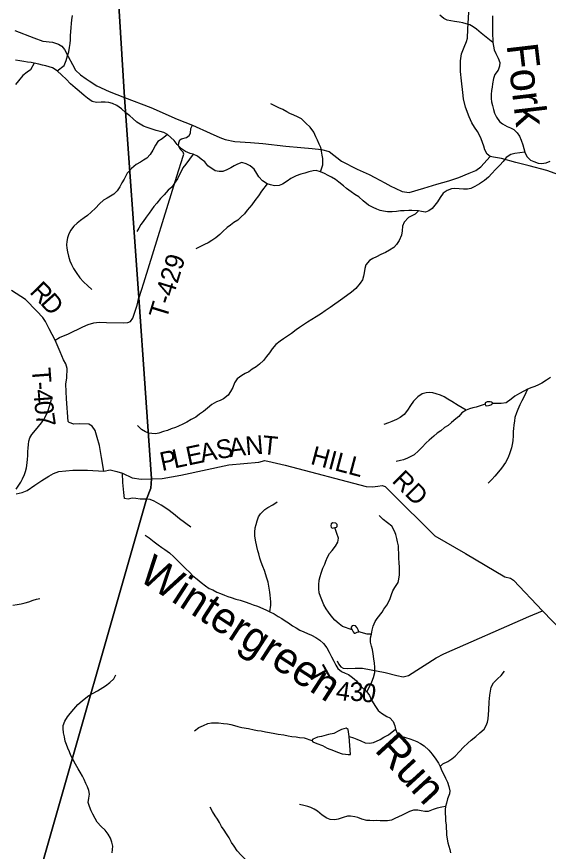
# Model space of a CAD drawing. Extents: x 1578669 to 1989827, y 208020 to 553079.
# Drawn here: x 1811019 to 1819546, y 411669 to 425058 of the extents above; entities that cross this region are included whole.
import ezdxf

# ---------------------------------------------------------------- set-up
doc = ezdxf.new("R2010")
doc.units = 0
for name, color, linetype in [('GM_X_County_Road', 7, 'Continuous'), ('GM_X_County_Road_Text', 7, 'Continuous'), ('GM_X_Minor_Lake', 7, 'Continuous'), ('GM_X_Minor_River', 7, 'Continuous'), ('GM_X_Minor_River_Text', 7, 'Continuous'), ('GM_X_Township', 7, 'Continuous'), ('GM_X_Township_Road', 7, 'Continuous'), ('GM_X_Township_Road_Text', 7, 'Continuous')]:
    doc.layers.add(name, color=color, linetype=linetype)

msp = doc.modelspace()

# ---------------------------------------------------------------- linework, layer by layer
at = {"layer": 'GM_X_County_Road'}
for points in [[(1818616, 422813), (1818564, 422853), (1818530, 422924), (1818513, 422982), (1818467, 423096), (1818451, 423136), (1818411, 423217), (1818363, 423287), (1818319, 423355), (1818278, 423449), (1818218, 423606), (1818188, 423738), (1818175, 423843), (1818155, 424031), (1818140, 424181), (1818136, 424350), (1818153, 424460), (1818195, 424570), (1818233, 424660), (1818250, 424716), (1818258, 424860), (1818273, 425133)], [(1810991, 424838), (1811295, 424721), (1811437, 424666), (1811595, 424648), (1811690, 424616), (1811744, 424584), (1811786, 424533), (1811844, 424421), (1811913, 424289), (1811965, 424198), (1812044, 424127), (1812134, 424060), (1812182, 424029)], [(1812182, 424029), (1812307, 423949), (1812501, 423856), (1812748, 423763), (1813169, 423600), (1813592, 423415), (1813837, 423317), (1814122, 423189), (1814280, 423121), (1814363, 423088), (1814518, 423056), (1814768, 423041), (1814968, 423023), (1815339, 422983), (1815579, 422958), (1815757, 422943), (1815910, 422926), (1816030, 422896), (1816228, 422742), (1816482, 422613), (1816672, 422524), (1816764, 422476), (1816922, 422391), (1817020, 422341), (1817090, 422307), (1817202, 422254), (1817314, 422240), (1817551, 422305), (1817759, 422373), (1817950, 422426), (1818110, 422480), (1818279, 422550), (1818383, 422593), (1818463, 422651), (1818616, 422813)], [(1819925, 422444), (1819525, 422590), (1819239, 422667), (1819023, 422720), (1818794, 422781), (1818667, 422804), (1818616, 422813)], [(1813170, 417646), (1813183, 417646), (1813354, 417647), (1813652, 417704), (1814421, 417871), (1814903, 417913), (1815002, 417937), (1815118, 417914), (1815327, 417865), (1816627, 417519), (1816725, 417516), (1816811, 417528), (1816880, 417536), (1816932, 417521), (1817022, 417431), (1817724, 416727), (1818217, 416444), (1818850, 416072), (1818942, 416048), (1818990, 416017), (1819456, 415529), (1819770, 415199)], [(1811011, 417404), (1811108, 417426), (1811186, 417458), (1811310, 417540), (1811425, 417616), (1811535, 417689), (1811610, 417731), (1811698, 417761), (1811922, 417783), (1812155, 417782), (1812415, 417767), (1812517, 417790), (1812627, 417764), (1812714, 417733)], [(1812714, 417733), (1812714, 417733), (1812870, 417660), (1813014, 417639), (1813170, 417646)]]:
    msp.add_lwpolyline(points, dxfattribs=at)
at = {"layer": 'GM_X_Minor_Lake'}
for points in [[(1818651, 418863), (1818635, 418875), (1818612, 418880), (1818592, 418880), (1818564, 418878), (1818534, 418864), (1818533, 418840), (1818541, 418820), (1818563, 418816), (1818587, 418820), (1818607, 418824), (1818625, 418832), (1818641, 418843)], [(1818641, 418843), (1818652, 418850), (1818654, 418856), (1818651, 418863)], [(1816124, 416862), (1816150, 416868), (1816160, 416882), (1816161, 416913), (1816137, 416932), (1816089, 416938), (1816063, 416924), (1816057, 416892), (1816065, 416868), (1816082, 416852)], [(1816082, 416852), (1816124, 416862)], [(1816507, 415192), (1816499, 415222), (1816483, 415256), (1816452, 415284), (1816422, 415291), (1816402, 415285), (1816384, 415267), (1816386, 415243), (1816399, 415219), (1816415, 415189), (1816433, 415169), (1816449, 415169), (1816481, 415182)], [(1816481, 415182), (1816507, 415192)], [(1816353, 413511), (1816336, 413623), (1816302, 413645), (1816268, 413634), (1816228, 413620), (1816186, 413599), (1816106, 413561), (1816020, 413544), (1815910, 413511), (1815844, 413498), (1815796, 413479), (1815772, 413469), (1815752, 413445), (1815767, 413425), (1815835, 413400), (1815924, 413364), (1815998, 413321), (1816099, 413286), (1816167, 413258), (1816242, 413231), (1816296, 413228), (1816336, 413222)], [(1816336, 413222), (1816372, 413219), (1816353, 413511)]]:
    msp.add_lwpolyline(points, dxfattribs=at)
at = {"layer": 'GM_X_Minor_River'}
for points in [[(1811666, 424189), (1811780, 424276), (1811815, 424357), (1811837, 424429), (1811854, 424497), (1811866, 424562), (1811875, 424630), (1811881, 424686), (1811884, 424756), (1811889, 424813), (1811893, 424887), (1811900, 424951), (1811906, 425009), (1811917, 425077)], [(1818656, 424644), (1818521, 424751), (1818467, 424792), (1818396, 424858), (1818341, 424895), (1818287, 424925), (1818231, 424944), (1818174, 424958), (1818118, 424969), (1818042, 424982), (1817982, 424992), (1817925, 425003), (1817869, 425029), (1817808, 425080)], [(1818653, 425074), (1818651, 425008), (1818650, 424952), (1818651, 424842), (1818653, 424758), (1818656, 424704), (1818656, 424644), (1818665, 424586), (1818677, 424528), (1818706, 424468), (1818743, 424392), (1818767, 424324), (1818766, 424262), (1818743, 424199), (1818691, 424131), (1818667, 424066), (1818652, 423982), (1818645, 423926), (1818637, 423876), (1818630, 423812), (1818630, 423743), (1818635, 423693), (1818651, 423633), (1818668, 423571), (1818686, 423513), (1818715, 423448), (1818762, 423378), (1818812, 423338), (1818889, 423297), (1818939, 423273), (1818991, 423250), (1819048, 423194), (1819083, 423140), (1819109, 423075), (1819136, 423001), (1819152, 422943), (1819169, 422887), (1819202, 422817), (1819260, 422757), (1819317, 422734), (1819383, 422710), (1819439, 422705), (1819513, 422716), (1819575, 422738)], [(1812832, 423465), (1812771, 423518), (1812698, 423582), (1812628, 423631), (1812555, 423667), (1812499, 423680), (1812439, 423687), (1812377, 423689), (1812300, 423684), (1812228, 423697), (1812157, 423751), (1812101, 423796), (1812024, 423862), (1811955, 423919), (1811881, 423981), (1811812, 424054), (1811743, 424122), (1811666, 424189), (1811596, 424236), (1811543, 424256), (1811489, 424271), (1811433, 424283), (1811377, 424296), (1811300, 424312), (1811250, 424321), (1811194, 424329), (1811132, 424340), (1811069, 424348), (1811001, 424359)], [(1811300, 424312), (1811239, 424203), (1811187, 424166), (1811118, 424112), (1811050, 424031), (1811001, 423970)], [(1815891, 422568), (1815928, 422683), (1815932, 422733), (1815928, 422783), (1815917, 422839), (1815909, 422903), (1815896, 422959), (1815871, 423015), (1815845, 423075), (1815818, 423129), (1815784, 423207), (1815725, 423284), (1815658, 423352), (1815587, 423417), (1815521, 423453), (1815464, 423478), (1815402, 423504), (1815352, 423531), (1815289, 423567), (1815223, 423598), (1815094, 423661)], [(1819169, 422887), (1819009, 422865), (1818947, 422848), (1818871, 422798), (1818823, 422733), (1818768, 422678), (1818698, 422604), (1818643, 422543), (1818587, 422486), (1818523, 422431), (1818442, 422377), (1818370, 422334), (1818304, 422301), (1818250, 422289), (1818184, 422292), (1818115, 422299), (1818049, 422303), (1817993, 422294), (1817923, 422271), (1817859, 422225), (1817814, 422158), (1817768, 422089), (1817727, 422037), (1817681, 421982), (1817629, 421942), (1817575, 421921), (1817513, 421933), (1817463, 421942), (1817359, 421949), (1817308, 421949), (1817234, 421946), (1817176, 421941), (1817114, 421935), (1817044, 421930), (1816968, 421929), (1816901, 421937), (1816849, 421948), (1816795, 421968), (1816735, 421995), (1816664, 422037), (1816575, 422104), (1816510, 422166), (1816442, 422207), (1816387, 422248), (1816311, 422300), (1816260, 422345), (1816188, 422403), (1816135, 422445), (1816069, 422486), (1816014, 422513), (1815956, 422541), (1815891, 422568), (1815823, 422590), (1815773, 422585), (1815707, 422569), (1815639, 422548), (1815577, 422531), (1815501, 422503), (1815417, 422460), (1815357, 422421), (1815284, 422374), (1815230, 422352), (1815157, 422345), (1815091, 422358), (1815037, 422378), (1814962, 422425), (1814904, 422491), (1814869, 422544), (1814826, 422610), (1814762, 422664), (1814701, 422697), (1814631, 422721), (1814563, 422694), (1814509, 422663), (1814455, 422635), (1814391, 422602), (1814325, 422577), (1814267, 422573), (1814201, 422584), (1814084, 422667), (1814035, 422727), (1813977, 422774), (1813918, 422820), (1813852, 422851), (1813801, 422865), (1813729, 422898), (1813664, 422940), (1813592, 423009), (1813543, 423071), (1813490, 423122), (1813438, 423168), (1813379, 423198), (1813319, 423217), (1813257, 423232), (1813178, 423260), (1813110, 423283), (1813052, 423303), (1812999, 423336), (1812949, 423368), (1812884, 423423), (1812832, 423465)], [(1813438, 423168), (1813354, 423099), (1813286, 423058), (1813247, 422998), (1813203, 422917), (1813160, 422849), (1813108, 422790), (1813056, 422759), (1813005, 422725), (1812937, 422688), (1812861, 422621), (1812790, 422548), (1812742, 422454), (1812707, 422395), (1812673, 422331), (1812630, 422262), (1812578, 422210), (1812526, 422177), (1812468, 422146), (1812414, 422112), (1812349, 422057), (1812285, 421988), (1812214, 421921), (1812156, 421867), (1812100, 421830), (1812042, 421787), (1811988, 421747), (1811935, 421700), (1811881, 421626), (1811852, 421559), (1811834, 421509), (1811825, 421451), (1811821, 421400), (1811826, 421342), (1811836, 421284), (1811851, 421214), (1811871, 421142), (1811898, 421081), (1811933, 421021), (1811973, 420953), (1812030, 420869), (1812093, 420802), (1812160, 420740), (1812224, 420681)], [(1813852, 422851), (1813735, 422694), (1813685, 422631), (1813654, 422565), (1813628, 422514), (1813598, 422458), (1813563, 422402), (1813507, 422325), (1813450, 422274), (1813386, 422201), (1813324, 422141), (1813265, 422066), (1813221, 422015), (1813184, 421961), (1813142, 421908), (1813095, 421840), (1813047, 421773), (1813013, 421723), (1812978, 421666), (1812944, 421612)], [(1815037, 422378), (1814946, 422261), (1814896, 422186), (1814841, 422107), (1814791, 422041), (1814718, 421952), (1814676, 421897), (1814620, 421845), (1814565, 421796), (1814505, 421755), (1814447, 421713), (1814395, 421674), (1814328, 421613), (1814276, 421565), (1814212, 421512), (1814149, 421465), (1814093, 421431), (1814033, 421402), (1813981, 421377), (1813895, 421332)], [(1817463, 421942), (1817409, 421890), (1817357, 421863), (1817303, 421836), (1817236, 421760), (1817210, 421695), (1817203, 421621), (1817190, 421555), (1817156, 421468), (1817113, 421406), (1817071, 421353), (1816999, 421310), (1816937, 421276), (1816861, 421241), (1816790, 421206), (1816732, 421179), (1816680, 421149), (1816620, 421078), (1816601, 421016), (1816591, 420950), (1816584, 420895), (1816564, 420839), (1816527, 420781), (1816457, 420700), (1816391, 420641), (1816252, 420535), (1816176, 420483), (1816120, 420444), (1816047, 420391), (1815967, 420338), (1815907, 420296), (1815821, 420243), (1815686, 420157), (1815620, 420116), (1815556, 420074), (1815500, 420033), (1815427, 419978), (1815361, 419934), (1815301, 419891), (1815247, 419854), (1815178, 419801), (1815116, 419731), (1815073, 419666), (1815029, 419606), (1814977, 419541), (1814914, 419484), (1814858, 419442), (1814796, 419401), (1814742, 419362), (1814686, 419332), (1814631, 419303), (1814557, 419246), (1814515, 419186), (1814484, 419111), (1814450, 419047), (1814413, 418988), (1814337, 418925), (1814285, 418901), (1814227, 418880), (1814151, 418837), (1814078, 418777), (1814014, 418724), (1813954, 418679), (1813892, 418636), (1813819, 418594), (1813749, 418553), (1813685, 418520), (1813617, 418488), (1813565, 418465), (1813499, 418444), (1813439, 418422), (1813375, 418403), (1813297, 418378), (1813247, 418368), (1813189, 418369), (1813139, 418379), (1813086, 418400), (1813022, 418436), (1812957, 418501)], [(1819584, 419269), (1819516, 419226), (1819444, 419179), (1819390, 419153), (1819332, 419128), (1819280, 419107), (1819214, 419081), (1819156, 419052), (1819083, 419015), (1819009, 418968), (1818949, 418922), (1818869, 418865), (1818793, 418850), (1818652, 418850)], [(1818227, 418746), (1818098, 418823), (1817997, 418887), (1817934, 418920), (1817874, 418958), (1817816, 418985), (1817747, 419006), (1817695, 419024), (1817641, 419029), (1817585, 419023), (1817521, 419006), (1817455, 418958), (1817383, 418889), (1817336, 418820), (1817286, 418747), (1817237, 418677), (1817171, 418626), (1817113, 418595), (1817035, 418563), (1816981, 418542), (1816907, 418515)], [(1819214, 419081), (1819159, 418964), (1819120, 418893), (1819090, 418833), (1819059, 418756), (1819035, 418702), (1819012, 418628), (1819002, 418574), (1818993, 418507), (1818987, 418453), (1818982, 418401), (1818982, 418339), (1818977, 418255), (1818969, 418194), (1818958, 418140), (1818932, 418060), (1818901, 417985), (1818858, 417907), (1818794, 417816), (1818747, 417757), (1818689, 417689), (1818639, 417634), (1818584, 417577)], [(1811013, 417478), (1811045, 417528), (1811086, 417593), (1811114, 417643), (1811145, 417712), (1811163, 417764), (1811175, 417820), (1811188, 417903), (1811191, 417957), (1811197, 418011), (1811200, 418083), (1811202, 418137), (1811207, 418193), (1811213, 418246), (1811228, 418304), (1811260, 418356), (1811320, 418425), (1811371, 418484), (1811417, 418544), (1811453, 418595), (1811490, 418665), (1811523, 418740), (1811541, 418794), (1811562, 418864), (1811578, 418919)], [(1818533, 418840), (1818389, 418794), (1818335, 418782), (1818283, 418767), (1818227, 418746), (1818161, 418702), (1818113, 418645), (1818061, 418607), (1817996, 418550), (1817940, 418501), (1817880, 418465), (1817821, 418414), (1817765, 418379), (1817709, 418331), (1817637, 418264), (1817586, 418219), (1817518, 418148), (1817462, 418094), (1817397, 418031), (1817341, 418000), (1817289, 417974), (1817225, 417951), (1817175, 417939), (1817107, 417922)], [(1815081, 415509), (1815098, 415617), (1815095, 415672), (1815089, 415724), (1815084, 415778), (1815078, 415828), (1815071, 415892), (1815051, 415984), (1815032, 416052), (1814995, 416172), (1814970, 416236), (1814939, 416307), (1814921, 416373), (1814904, 416439), (1814890, 416491), (1814873, 416559), (1814852, 416659), (1814838, 416731), (1814839, 416790), (1814846, 416858), (1814858, 416912), (1814876, 416972), (1814897, 417035), (1814931, 417085), (1814998, 417152), (1815050, 417184), (1815128, 417229), (1815196, 417276)], [(1816634, 414227), (1816683, 414318), (1816715, 414388), (1816744, 414457), (1816764, 414539), (1816765, 414625), (1816756, 414689), (1816746, 414759), (1816739, 414837), (1816728, 414904), (1816712, 414962), (1816697, 415026), (1816697, 415094), (1816708, 415152), (1816720, 415218), (1816739, 415282), (1816772, 415353), (1816804, 415403), (1816879, 415504), (1816911, 415555), (1816955, 415615), (1816982, 415666), (1817010, 415722), (1817029, 415788), (1817055, 415845), (1817087, 415901), (1817136, 415982), (1817150, 416032), (1817159, 416106), (1817162, 416177), (1817160, 416227), (1817153, 416297), (1817149, 416371), (1817148, 416451), (1817145, 416517), (1817141, 416571), (1817130, 416633), (1817118, 416687), (1817103, 416751), (1817081, 416807), (1817036, 416883), (1816967, 416938), (1816897, 416994), (1816836, 417057)], [(1816399, 415219), (1816248, 415274), (1816193, 415317), (1816123, 415375), (1816064, 415444), (1816019, 415504), (1815983, 415558), (1815948, 415622), (1815922, 415676), (1815891, 415757), (1815872, 415815), (1815866, 415879), (1815865, 415944), (1815872, 416018), (1815888, 416078), (1815901, 416130), (1815931, 416209), (1815962, 416273), (1815980, 416324), (1816006, 416388), (1816039, 416444), (1816077, 416495), (1816132, 416566), (1816170, 416628), (1816179, 416692), (1816157, 416766), (1816124, 416862)], [(1813081, 416738), (1813147, 416695), (1813224, 416632), (1813289, 416584), (1813345, 416545), (1813398, 416513), (1813468, 416458), (1813541, 416394), (1813606, 416329), (1813660, 416275), (1813729, 416204), (1813796, 416140), (1813845, 416088), (1813913, 416035), (1813978, 415983), (1814046, 415928), (1814109, 415887), (1814167, 415861), (1814232, 415826), (1814286, 415806), (1814351, 415777), (1814405, 415757), (1814461, 415740), (1814534, 415716), (1814606, 415695), (1814686, 415672), (1814761, 415644), (1814815, 415625), (1814883, 415601), (1814966, 415564), (1815026, 415537), (1815081, 415509), (1815147, 415476), (1815214, 415436), (1815272, 415403), (1815325, 415367), (1815377, 415334), (1815446, 415286), (1815502, 415253), (1815561, 415217), (1815623, 415192), (1815685, 415162), (1815748, 415137), (1815816, 415099), (1815881, 415056), (1815941, 415000), (1815992, 414931), (1816031, 414865), (1816070, 414791), (1816104, 414719), (1816137, 414653), (1816169, 414602), (1816232, 414552), (1816288, 414526), (1816339, 414503), (1816407, 414457), (1816470, 414402), (1816513, 414340), (1816581, 414273), (1816634, 414227), (1816677, 414167), (1816707, 414106), (1816738, 414048), (1816774, 413994), (1816819, 413930), (1816872, 413887), (1816954, 413833), (1817005, 413810), (1817057, 413752), (1817084, 413684), (1817094, 413630), (1817123, 413562), (1817184, 413517), (1817258, 413496), (1817324, 413474), (1817383, 413453), (1817439, 413431), (1817495, 413398), (1817556, 413362), (1817629, 413293), (1817685, 413229), (1817742, 413147), (1817783, 413082), (1817813, 413028), (1817840, 412962), (1817867, 412910), (1817897, 412842), (1817930, 412776), (1817953, 412708), (1817965, 412638), (1817964, 412588), (1817932, 412512), (1817911, 412443), (1817897, 412387), (1817892, 412337), (1817892, 412281), (1817895, 412211), (1817899, 412157), (1817906, 412089), (1817908, 412036), (1817911, 411986)], [(1810959, 415617), (1811027, 415626), (1811089, 415637), (1811155, 415653), (1811213, 415670), (1811285, 415695), (1811337, 415711), (1811393, 415726)], [(1816708, 415152), (1816640, 415153), (1816507, 415192)], [(1817813, 413028), (1817855, 413070), (1817933, 413111), (1817999, 413154), (1818051, 413196), (1818122, 413271), (1818188, 413340), (1818255, 413401), (1818311, 413450), (1818383, 413510), (1818448, 413567), (1818516, 413630), (1818552, 413686), (1818569, 413739), (1818581, 413793), (1818586, 413863), (1818592, 413935), (1818598, 414064), (1818604, 414118), (1818607, 414174), (1818632, 414304), (1818666, 414373), (1818732, 414436), (1818789, 414488), (1818845, 414561)], [(1812552, 411642), (1812557, 411696), (1812561, 411750), (1812548, 411816), (1812522, 411880), (1812487, 411942), (1812438, 412006), (1812372, 412069), (1812311, 412135), (1812276, 412197), (1812240, 412262), (1812215, 412316), (1812189, 412386), (1812168, 412452), (1812175, 412520), (1812185, 412587), (1812176, 412645), (1812156, 412701), (1812129, 412754), (1812103, 412818), (1812074, 412872), (1812035, 412940), (1812007, 412992), (1811964, 413068), (1811925, 413137), (1811889, 413205), (1811864, 413263), (1811839, 413325), (1811817, 413383), (1811798, 413435), (1811784, 413503), (1811771, 413571), (1811767, 413639), (1811766, 413689), (1811790, 413755), (1811837, 413826), (1811877, 413878), (1811936, 413951), (1812002, 414022), (1812071, 414083), (1812127, 414133), (1812179, 414166), (1812245, 414203), (1812317, 414244), (1812446, 414325), (1812514, 414374), (1812576, 414436), (1812611, 414501)], [(1813870, 413603), (1813940, 413654), (1814016, 413687), (1814084, 413719), (1814144, 413732), (1814202, 413729), (1814258, 413729), (1814336, 413720), (1814399, 413716), (1814453, 413703), (1814513, 413688), (1814565, 413672), (1814630, 413655), (1814738, 413638), (1814827, 413618), (1814881, 413609), (1814943, 413599), (1815011, 413586), (1815072, 413577), (1815160, 413559), (1815212, 413550), (1815305, 413535), (1815373, 413521), (1815433, 413512), (1815501, 413503), (1815558, 413495), (1815628, 413488), (1815752, 413445)], [(1816353, 413511), (1816420, 413489), (1816476, 413466), (1816537, 413442), (1816611, 413409), (1816679, 413402), (1816743, 413414), (1816847, 413463), (1816911, 413498), (1816981, 413535), (1817094, 413630)], [(1817897, 412387), (1817839, 412379), (1817763, 412362), (1817697, 412337), (1817621, 412308), (1817567, 412306), (1817505, 412319), (1817455, 412329), (1817386, 412328), (1817322, 412307), (1817265, 412281), (1817205, 412250), (1817143, 412222), (1817087, 412193), (1817029, 412168), (1816967, 412158), (1816915, 412157), (1816847, 412159), (1816792, 412162), (1816740, 412160), (1816686, 412161), (1816636, 412165), (1816556, 412182), (1816493, 412209), (1816443, 412223), (1816373, 412230), (1816323, 412232), (1816255, 412209), (1816177, 412182), (1816120, 412176), (1816046, 412179), (1815992, 412200), (1815921, 412250), (1815843, 412315), (1815790, 412347), (1815740, 412372), (1815688, 412390), (1815623, 412405), (1815557, 412417)], [(1814753, 411058), (1814768, 411130), (1814786, 411185), (1814801, 411261), (1814801, 411325), (1814794, 411377), (1814776, 411429), (1814735, 411493), (1814684, 411540), (1814620, 411604), (1814557, 411677), (1814508, 411753), (1814467, 411811), (1814425, 411885), (1814384, 411950), (1814345, 412010), (1814307, 412068), (1814272, 412130), (1814238, 412186), (1814205, 412237), (1814160, 412307), (1814122, 412375)], [(1817911, 411986), (1817913, 411932), (1817924, 411862), (1817936, 411804), (1817953, 411750), (1817967, 411698), (1817976, 411646)]]:
    msp.add_lwpolyline(points, dxfattribs=at)
at = {"layer": 'GM_X_Township'}
for points in [[(1794614, 432491), (1800878, 431987), (1805343, 431619), (1806251, 431556), (1812296, 431154), (1812748, 423763), (1812981, 420551), (1813183, 417646), (1813169, 417495), (1813101, 417318), (1811396, 411352), (1811003, 410233), (1810653, 409191), (1809037, 404233), (1808867, 403681), (1808758, 403152), (1808680, 402775), (1808603, 402344), (1807250, 395261), (1804835, 395344), (1793085, 395748)], [(1811396, 411352), (1813101, 417318), (1813169, 417495), (1813183, 417646), (1812981, 420551), (1812748, 423763), (1812296, 431154), (1815260, 430933), (1818512, 430701), (1822111, 430472), (1822276, 430466), (1826767, 430168), (1828657, 430067), (1832918, 429813)]]:
    msp.add_lwpolyline(points, dxfattribs=at)
at = {"layer": 'GM_X_Township_Road'}
for points in [[(1812982, 420554), (1813057, 420787), (1813588, 422500), (1813692, 422823), (1813698, 422852), (1813691, 422887), (1813643, 422931), (1813616, 422988), (1813618, 423034), (1813634, 423081), (1813664, 423101), (1813742, 423120), (1813785, 423150), (1813806, 423189), (1813814, 423263), (1813837, 423317)], [(1812415, 417767), (1812382, 417988), (1812350, 418180), (1812311, 418306), (1812279, 418421), (1812229, 418491), (1812177, 418523), (1812033, 418526), (1811935, 418522), (1811859, 418546), (1811847, 418566), (1811818, 418927), (1811808, 419162), (1811824, 419264), (1811829, 419415), (1811809, 419488), (1811772, 419555), (1811717, 419680), (1811634, 419869), (1811542, 420048), (1811480, 420167), (1811439, 420234), (1811345, 420333), (1811163, 420519), (1810938, 420665)], [(1811634, 419869), (1811708, 419912), (1811851, 419972), (1812080, 420083), (1812168, 420121), (1812258, 420147), (1812341, 420156), (1812462, 420153), (1812738, 420147), (1812801, 420151), (1812847, 420167), (1812884, 420219), (1812950, 420432), (1812981, 420551), (1812982, 420554)], [(1813813, 416871), (1813631, 417003), (1813535, 417082), (1813446, 417150), (1813338, 417223), (1813226, 417288), (1813161, 417314), (1813101, 417318), (1813001, 417317), (1812933, 417327), (1812870, 417333), (1812805, 417320), (1812750, 417330), (1812740, 417427), (1812721, 417586), (1812714, 417733)], [(1816159, 414725), (1816182, 414678), (1816218, 414630), (1816256, 414607), (1816328, 414599), (1816447, 414607), (1816564, 414608), (1816931, 414539), (1817119, 414491), (1817217, 414468), (1817304, 414491), (1817748, 414775), (1817869, 414834), (1819236, 415434), (1819456, 415529)]]:
    msp.add_lwpolyline(points, dxfattribs=at)

# ---------------------------------------------------------------- texts
at = {"layer": 'GM_X_County_Road_Text'}
for s, rotation, p in [('A', 7.2393, (1814440, 417990)), ('N', 4.5912, (1814698, 418023)), ('T', 354.2306, (1814947, 418044)), ('E', 11.9185, (1813769, 417856)), ('A', 11.7571, (1813988, 417902)), ('S', 10.0528, (1814244, 417956)), ('HILL', 345.1974, (1815718, 417886)), ('P', 11.747, (1813350, 417768)), ('L', 11.9208, (1813549, 417810)), ('RD', 315.0067, (1817024, 417601))]:
    msp.add_text(s, height=300, rotation=rotation, dxfattribs=at).set_placement(p)
at = {"layer": 'GM_X_Minor_River_Text'}
for s, height, rotation, p in [('Fork', 500, 276.6629, (1818876, 424606)), ('Wintergreen', 500.01, 327.0338, (1812952, 416031)), ('Run', 500, 312.5277, (1816746, 413285))]:
    msp.add_text(s, height=height, rotation=rotation, dxfattribs=at).set_placement(p)
at = {"layer": 'GM_X_Township_Road_Text'}
for s, rotation, p in [('T-429', 72.9299, (1813421, 420190)), ('R', 314.5502, (1811213, 420631)), ('D', 311.9721, (1811384, 420458)), ('T', 274.2508, (1811261, 419418)), ('-', 274.2552, (1811278, 419194)), ('4', 274.4248, (1811287, 419071)), ('0', 275.2712, (1811302, 418882)), ('7', 278.3964, (1811321, 418680)), ('T', 298.6737, (1815677, 414539)), ('-', 326.1822, (1815890, 414227)), ('4', 351.7501, (1816127, 414107)), ('3', 1.4037, (1816365, 414077)), ('0', 349.4596, (1816533, 414083))]:
    msp.add_text(s, height=300, rotation=rotation, dxfattribs=at).set_placement(p)

doc.saveas('drawing.dxf')
